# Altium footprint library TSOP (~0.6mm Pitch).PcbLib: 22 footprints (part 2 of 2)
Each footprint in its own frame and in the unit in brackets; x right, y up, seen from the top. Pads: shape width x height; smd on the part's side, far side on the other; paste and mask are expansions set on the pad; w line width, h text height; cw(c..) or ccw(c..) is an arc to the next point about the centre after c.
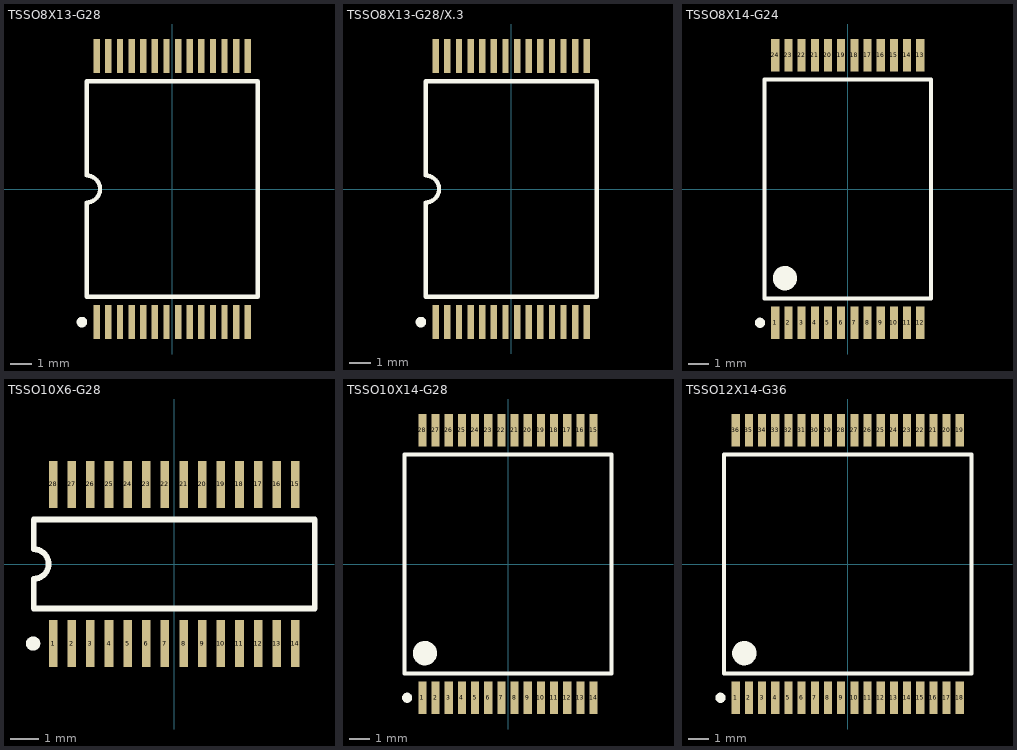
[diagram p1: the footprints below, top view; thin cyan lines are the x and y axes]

## TSSO8X13-G28 [mm]
pads (28):
  rect 0.3x1.6 smd: 1(-3.575,-6.3) 2(-3.025,-6.3) 3(-2.475,-6.3) 4(-1.925,-6.3) 5(-1.375,-6.3) 6(-0.825,-6.3) 7(-0.275,-6.3) 8(0.275,-6.3) 9(0.825,-6.3) 10(1.375,-6.3) 11(1.925,-6.3) 12(2.475,-6.3) 13(3.025,-6.3) 14(3.575,-6.3) 15(3.575,6.3) 16(3.025,6.3) 17(2.475,6.3) 18(1.925,6.3) 19(1.375,6.3) 20(0.825,6.3) 21(0.275,6.3) 22(-0.275,6.3) 23(-0.825,6.3) 24(-1.375,6.3) 25(-1.925,6.3) 26(-2.475,6.3) 27(-3.025,6.3) 28(-3.575,6.3)
Top Overlay:
  circle w0.25: c-4.275,-6.3 r0.125
  lines w0.2: -4.05,-5.1 4.05,-5.1 4.05,5.1 -4.05,5.1 -4.05,0.635 cw(c-4.05,0) -4.05,-0.635 -4.05,-5.1

## TSSO8X13-G28/X.3 [mm]
pads (28):
  rect 0.3x1.6 smd: 1(0.275,-6.3) 2(0.825,-6.3) 3(1.375,-6.3) 4(1.925,-6.3) 5(2.475,-6.3) 6(3.025,-6.3) 7(3.575,-6.3) 8(3.575,6.3) 9(3.025,6.3) 10(2.475,6.3) 11(1.925,6.3) 12(1.375,6.3) 13(0.825,6.3) 14(0.275,6.3) 15(-0.275,6.3) 16(-0.825,6.3) 17(-1.375,6.3) 18(-1.925,6.3) 19(-2.475,6.3) 20(-3.025,6.3) 21(-3.575,6.3) 22(-3.575,-6.3) 23(-3.025,-6.3) 24(-2.475,-6.3) 25(-1.925,-6.3) 26(-1.375,-6.3) 27(-0.825,-6.3) 28(-0.275,-6.3)
Top Overlay:
  circle w0.25: c-4.275,-6.3 r0.125
  lines w0.2: -4.05,-5.1 -4.05,-0.635 ccw(c-4.05,0) -4.05,0.635 -4.05,5.1 4.05,5.1 4.05,-5.1 -4.05,-5.1

## TSSO8X14-G24 [mm]
pads (24):
  rect 0.4x1.6 smd: 1(-3.575,-6.6) 2(-2.925,-6.6) 3(-2.275,-6.6) 4(-1.625,-6.6) 5(-0.975,-6.6) 6(-0.325,-6.6) 7(0.325,-6.6) 8(0.975,-6.6) 9(1.625,-6.6) 10(2.275,-6.6) 11(2.925,-6.6) 12(3.575,-6.6) 13(3.575,6.6) 14(2.925,6.6) 15(2.275,6.6) 16(1.625,6.6) 17(0.975,6.6) 18(0.325,6.6) 19(-0.325,6.6) 20(-0.975,6.6) 21(-1.625,6.6) 22(-2.275,6.6) 23(-2.925,6.6) 24(-3.575,6.6)
Top Overlay:
  circle w0.6: c-3.1,-4.4 r0.3
  circle w0.25: c-4.325,-6.6 r0.125
  lines w0.2: -4.1,-5.4 4.1,-5.4 4.1,5.4 -4.1,5.4 -4.1,-0.635 -4.1,-5.4

## TSSO10X6-G28 [mm]
pads (28):
  rect 0.3x1.65 smd: 1(-4.225,-2.775) 2(-3.575,-2.775) 3(-2.925,-2.775) 4(-2.275,-2.775) 5(-1.625,-2.775) 6(-0.975,-2.775) 7(-0.325,-2.775) 8(0.325,-2.775) 9(0.975,-2.775) 10(1.625,-2.775) 11(2.275,-2.775) 12(2.925,-2.775) 13(3.575,-2.775) 14(4.225,-2.775) 15(4.225,2.775) 16(3.575,2.775) 17(2.925,2.775) 18(2.275,2.775) 19(1.625,2.775) 20(0.975,2.775) 21(0.325,2.775) 22(-0.325,2.775) 23(-0.975,2.775) 24(-1.625,2.775) 25(-2.275,2.775) 26(-2.925,2.775) 27(-3.575,2.775) 28(-4.225,2.775)
Top Overlay:
  circle w0.25: c-4.925,-2.775 r0.125
  lines w0.2: -4.9,-1.55 4.9,-1.55 4.9,1.55 -4.9,1.55 -4.9,0.517 cw(c-4.9,0) -4.9,-0.517 -4.9,-1.55

## TSSO10X14-G28 [mm]
pads (28):
  rect 0.4x1.6 smd: 1(-4.225,-6.6) 2(-3.575,-6.6) 3(-2.925,-6.6) 4(-2.275,-6.6) 5(-1.625,-6.6) 6(-0.975,-6.6) 7(-0.325,-6.6) 8(0.325,-6.6) 9(0.975,-6.6) 10(1.625,-6.6) 11(2.275,-6.6) 12(2.925,-6.6) 13(3.575,-6.6) 14(4.225,-6.6) 15(4.225,6.6) 16(3.575,6.6) 17(2.925,6.6) 18(2.275,6.6) 19(1.625,6.6) 20(0.975,6.6) 21(0.325,6.6) 22(-0.325,6.6) 23(-0.975,6.6) 24(-1.625,6.6) 25(-2.275,6.6) 26(-2.925,6.6) 27(-3.575,6.6) 28(-4.225,6.6)
Top Overlay:
  circle w0.6: c-4.1,-4.4 r0.3
  circle w0.25: c-4.975,-6.6 r0.125
  lines w0.2: -5.1,-5.4 5.1,-5.4 5.1,5.4 -5.1,5.4 -5.1,-0.635 -5.1,-5.4

## TSSO12X14-G36 [mm]
pads (36):
  rect 0.4x1.6 smd: 1(-5.525,-6.6) 2(-4.875,-6.6) 3(-4.225,-6.6) 4(-3.575,-6.6) 5(-2.925,-6.6) 6(-2.275,-6.6) 7(-1.625,-6.6) 8(-0.975,-6.6) 9(-0.325,-6.6) 10(0.325,-6.6) 11(0.975,-6.6) 12(1.625,-6.6) 13(2.275,-6.6) 14(2.925,-6.6) 15(3.575,-6.6) 16(4.225,-6.6) 17(4.875,-6.6) 18(5.525,-6.6) 19(5.525,6.6) 20(4.875,6.6) 21(4.225,6.6) 22(3.575,6.6) 23(2.925,6.6) 24(2.275,6.6) 25(1.625,6.6) 26(0.975,6.6) 27(0.325,6.6) 28(-0.325,6.6) 29(-0.975,6.6) 30(-1.625,6.6) 31(-2.275,6.6) 32(-2.925,6.6) 33(-3.575,6.6) 34(-4.225,6.6) 35(-4.875,6.6) 36(-5.525,6.6)
Top Overlay:
  circle w0.6: c-5.1,-4.4 r0.3
  circle w0.25: c-6.275,-6.6 r0.125
  lines w0.2: -6.1,-5.4 6.1,-5.4 6.1,5.4 -6.1,5.4 -6.1,-0.635 -6.1,-5.4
